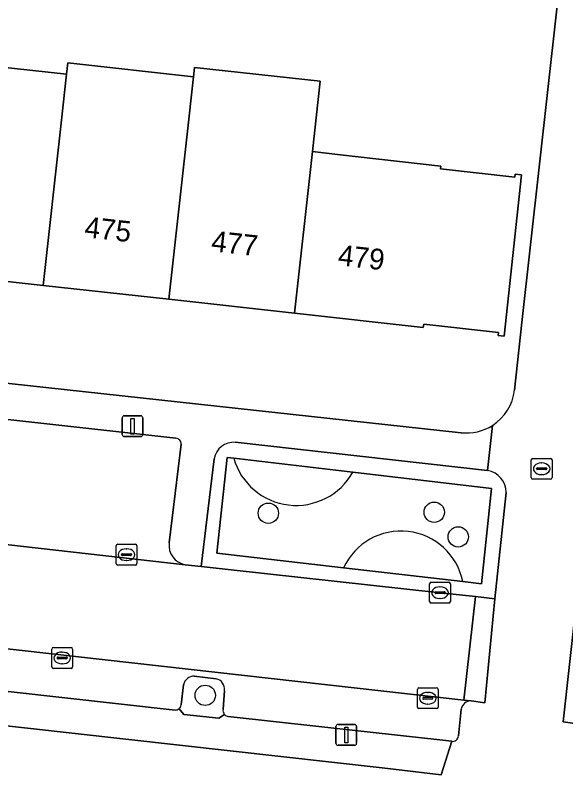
# Model space of a CAD drawing. Extents: x 161928 to 163071, y 386474 to 387428.
# Drawn here: x 162072.46 to 162098.94, y 387040.09 to 387076.6 of the extents above; entities that cross this region are included whole.
import ezdxf

# ---------------------------------------------------------------- set-up
doc = ezdxf.new("R2010")
doc.units = 0
for name, color, linetype in [('IMGEO_Boom', 7, 'Continuous'), ('IMGEO_Brandkraan', 7, 'Continuous'), ('IMGEO_Erf', 7, 'Continuous'), ('IMGEO_Groenvoorziening', 7, 'Continuous'), ('IMGEO_Kolk', 7, 'Continuous'), ('IMGEO_Lichtmast', 7, 'Continuous'), ('IMGEO_Pand', 7, 'Continuous'), ('IMGEO_Pand_nummerreeks', 7, 'Continuous'), ('IMGEO_Parkeervlak_open', 7, 'Continuous'), ('IMGEO_Rijbaan_lokaal_open', 7, 'Continuous'), ('IMGEO_Voetpad_open', 7, 'Continuous')]:
    doc.layers.add(name, color=color, linetype=linetype)

msp = doc.modelspace()

# ---------------------------------------------------------------- linework, layer by layer
at = {"layer": 'IMGEO_Boom'}
for centre in [(162084.633, 387052.664), (162092.612, 387052.707), (162093.767, 387051.525), (162081.599, 387043.908)]:
    msp.add_circle(centre, 0.489, dxfattribs=at)
at = {"layer": 'IMGEO_Brandkraan'}
for p, q in [((162097.352, 387055.299), (162098.204, 387055.299)), ((162097.277, 387054.373), (162097.277, 387055.225)), ((162097.765, 387055.079), (162097.79, 387055.079)), ((162098.278, 387055.225), (162098.278, 387054.373)), ((162097.536, 387054.793), (162097.536, 387054.805)), ((162097.974, 387054.756), (162097.576, 387054.756)), ((162097.579, 387054.842), (162097.977, 387054.842)), ((162097.788, 387054.519), (162097.763, 387054.519)), ((162098.02, 387054.805), (162098.02, 387054.793)), ((162098.204, 387054.299), (162097.352, 387054.299))]:
    msp.add_line(p, q, dxfattribs=at)
for points in [[(162097.352, 387055.299), (162098.204, 387055.299)], [(162097.277, 387054.373), (162097.277, 387055.225)], [(162098.278, 387055.225), (162098.278, 387054.373)], [(162098.204, 387054.299), (162097.352, 387054.299)]]:
    msp.add_lwpolyline(points, dxfattribs=at)
for centre, radius, start, end in [((162097.354, 387055.223), 0.0765, 91.552, 178.448), ((162097.354, 387055.223), 0.0765, 91.552, 178.448), ((162098.202, 387055.223), 0.0765, 1.552, 88.448), ((162098.202, 387055.223), 0.0765, 1.552, 88.448), ((162097.576, 387054.802), 0.0403, 85.8775, 175.7526), ((162097.573, 387054.792), 0.0366, 178.938, 274.7102), ((162097.977, 387054.799), 0.043, 264.8664, 352.4533), ((162097.981, 387054.804), 0.0386, 1.7309, 96.639), ((162097.354, 387054.375), 0.0765, 181.552, 268.448), ((162097.354, 387054.375), 0.0765, 181.552, 268.448), ((162098.202, 387054.375), 0.0765, 271.552, 358.448), ((162098.202, 387054.375), 0.0765, 271.552, 358.448)]:
    msp.add_arc(centre, radius, start, end, dxfattribs=at)
for centre, major_axis, ratio, start_param, end_param in [((162097.764, 387054.799), (-0.387, 0.002), 0.722429, 4.712389, 7.853982), ((162097.789, 387054.799), (-0.39, 0.002), 0.717154, 1.570796, 4.712389)]:
    msp.add_ellipse(centre, major_axis=major_axis, ratio=ratio, start_param=start_param, end_param=end_param, dxfattribs=at)
at = {"layer": 'IMGEO_Erf'}
for points in [[(162096.466, 387058.574), (162096.828, 387061.825), (162098.906, 387080.512)], [(162068.886, 387074.43), (162074.93, 387073.76), (162074.99, 387074.308), (162081.034, 387073.639), (162081.084, 387074.093), (162087.129, 387073.423), (162086.755, 387070.048), (162087.961, 387069.911), (162092.929, 387069.349), (162092.914, 387069.214), (162096.491, 387068.817), (162096.507, 387068.965), (162096.805, 387068.934), (162095.977, 387061.165), (162095.679, 387061.197), (162095.695, 387061.347), (162092.103, 387061.743), (162092.086, 387061.59), (162085.894, 387062.276), (162079.85, 387062.945), (162073.806, 387063.615), (162067.762, 387064.284)], [(162054.959, 387060.765), (162093.91, 387056.533)], [(162092.941, 387040.089), (162090.107, 387040.42), (162053.258, 387044.538), (162053.273, 387044.667), (162053.232, 387044.673), (162052.938, 387041.772), (162059.112, 387041.065), (162065.136, 387040.375), (162071.16, 387039.686), (162077.183, 387038.996), (162083.207, 387038.307), (162089.378, 387037.6), (162089.04, 387034.471), (162092.569, 387034.041), (162091.726, 387026.452), (162088.106, 387026.85), (162088.494, 387030.02)]]:
    msp.add_lwpolyline(points, dxfattribs=at)
for centre, radius, start, end in [((162094.168, 387058.829), 2.312, 302.701, 353.6728), ((162094.172, 387058.826), 2.307, 263.4876, 302.6627)]:
    msp.add_arc(centre, radius, start, end, dxfattribs=at)
at = {"layer": 'IMGEO_Groenvoorziening'}
for points in [[(162095.178, 387054.709), (162083.034, 387056.07)], [(162082.033, 387055.276), (162081.394, 387050.101), (162082.851, 387049.942), (162092.891, 387048.842), (162094.599, 387048.655), (162095.518, 387048.554), (162096.065, 387053.656)], [(162082.966, 387055.308), (162082.647, 387055.346), (162082.154, 387050.736), (162088.254, 387050.035)], [(162088.696, 387054.635), (162082.966, 387055.308)], [(162093.984, 387049.377), (162094.888, 387049.273), (162095.365, 387053.851), (162088.696, 387054.635)], [(162088.254, 387050.035), (162093.984, 387049.377)], [(162082.123, 387044.704), (162081.073, 387044.832)], [(162080.556, 387044.415), (162080.434, 387043.446)], [(162082.454, 387043.229), (162082.525, 387044.14)], [(162080.337, 387043.267), (162080.564, 387042.994), (162082.252, 387042.814), (162082.524, 387042.994)]]:
    msp.add_lwpolyline(points, dxfattribs=at)
msp.add_lwpolyline([(162093.984, 387049.377), (162088.254, 387050.035), (162082.154, 387050.736), (162082.647, 387055.346), (162082.966, 387055.308), (162088.696, 387054.635), (162095.365, 387053.851), (162094.888, 387049.273)], close=True, dxfattribs=at)
for centre, radius, start, end in [((162082.962, 387055.133), 0.94, 85.5971, 171.2463), ((162085.971, 387056.162), 3.124, 195.8703, 330.732), ((162085.971, 387056.162), 3.124, 195.8703, 330.732), ((162095.025, 387053.68), 1.04, 358.6594, 81.5592), ((162091.012, 387048.774), 3.032, 11.4606, 155.4377), ((162091.012, 387048.774), 3.032, 11.4606, 155.4377), ((162081.071, 387044.306), 0.526, 89.7371, 168.0405), ((162082.019, 387044.205), 0.51, 352.7293, 78.2306), ((162080.147, 387043.486), 0.29, 310.984, 352.1095), ((162082.752, 387043.19), 0.301, 172.5508, 220.6239)]:
    msp.add_arc(centre, radius, start, end, dxfattribs=at)
at = {"layer": 'IMGEO_Kolk'}
for p, q in [((162077.312, 387050.244), (162077.312, 387051.096)), ((162077.387, 387051.17), (162078.239, 387051.17)), ((162077.8, 387050.95), (162077.825, 387050.95)), ((162078.313, 387051.096), (162078.313, 387050.244)), ((162077.571, 387050.664), (162077.571, 387050.676)), ((162078.009, 387050.627), (162077.611, 387050.627)), ((162077.614, 387050.713), (162078.012, 387050.713)), ((162078.055, 387050.676), (162078.055, 387050.664)), ((162078.239, 387050.17), (162077.387, 387050.17)), ((162077.823, 387050.39), (162077.798, 387050.39)), ((162092.39, 387048.416), (162092.39, 387049.268)), ((162092.465, 387049.342), (162093.317, 387049.342)), ((162092.878, 387049.122), (162092.903, 387049.122)), ((162093.391, 387049.268), (162093.391, 387048.416)), ((162092.649, 387048.836), (162092.649, 387048.848)), ((162093.087, 387048.799), (162092.689, 387048.799)), ((162092.692, 387048.885), (162093.09, 387048.885)), ((162093.133, 387048.848), (162093.133, 387048.836)), ((162093.317, 387048.342), (162092.465, 387048.342)), ((162092.901, 387048.562), (162092.876, 387048.562)), ((162074.22, 387045.28), (162074.22, 387046.132)), ((162074.295, 387046.206), (162075.147, 387046.206)), ((162075.221, 387046.132), (162075.221, 387045.28)), ((162074.522, 387045.749), (162074.92, 387045.749)), ((162074.708, 387045.986), (162074.733, 387045.986)), ((162074.479, 387045.7), (162074.479, 387045.712)), ((162074.917, 387045.663), (162074.519, 387045.663)), ((162074.731, 387045.426), (162074.706, 387045.426)), ((162074.963, 387045.712), (162074.963, 387045.7)), ((162075.147, 387045.206), (162074.295, 387045.206)), ((162091.799, 387043.345), (162091.799, 387044.197)), ((162091.874, 387044.271), (162092.726, 387044.271)), ((162092.287, 387044.051), (162092.312, 387044.051)), ((162092.8, 387044.197), (162092.8, 387043.345)), ((162092.058, 387043.765), (162092.058, 387043.777)), ((162092.496, 387043.728), (162092.098, 387043.728)), ((162092.101, 387043.814), (162092.499, 387043.814)), ((162092.542, 387043.777), (162092.542, 387043.765)), ((162092.726, 387043.271), (162091.874, 387043.271)), ((162092.31, 387043.491), (162092.285, 387043.491))]:
    msp.add_line(p, q, dxfattribs=at)
for points in [[(162077.312, 387050.244), (162077.312, 387051.096)], [(162077.387, 387051.17), (162078.239, 387051.17)], [(162078.313, 387051.096), (162078.313, 387050.244)], [(162078.239, 387050.17), (162077.387, 387050.17)], [(162092.39, 387048.416), (162092.39, 387049.268)], [(162092.465, 387049.342), (162093.317, 387049.342)], [(162093.391, 387049.268), (162093.391, 387048.416)], [(162093.317, 387048.342), (162092.465, 387048.342)], [(162074.22, 387045.28), (162074.22, 387046.132)], [(162074.295, 387046.206), (162075.147, 387046.206)], [(162075.221, 387046.132), (162075.221, 387045.28)], [(162075.147, 387045.206), (162074.295, 387045.206)], [(162091.799, 387043.345), (162091.799, 387044.197)], [(162091.874, 387044.271), (162092.726, 387044.271)], [(162092.8, 387044.197), (162092.8, 387043.345)], [(162092.726, 387043.271), (162091.874, 387043.271)]]:
    msp.add_lwpolyline(points, dxfattribs=at)
for centre, radius, start, end in [((162077.389, 387051.094), 0.0765, 91.552, 178.448), ((162077.389, 387051.094), 0.0765, 91.552, 178.448), ((162078.237, 387051.094), 0.0765, 1.552, 88.448), ((162078.237, 387051.094), 0.0765, 1.552, 88.448), ((162077.611, 387050.673), 0.0403, 85.8775, 175.7526), ((162077.608, 387050.663), 0.0366, 178.938, 274.7102), ((162078.012, 387050.67), 0.043, 264.8664, 352.4533), ((162078.016, 387050.675), 0.0386, 1.7309, 96.639), ((162077.389, 387050.246), 0.0765, 181.552, 268.448), ((162077.389, 387050.246), 0.0765, 181.552, 268.448), ((162078.237, 387050.246), 0.0765, 271.552, 358.448), ((162078.237, 387050.246), 0.0765, 271.552, 358.448), ((162092.467, 387049.266), 0.0765, 91.552, 178.448), ((162092.467, 387049.266), 0.0765, 91.552, 178.448), ((162093.315, 387049.266), 0.0765, 1.552, 88.448), ((162093.315, 387049.266), 0.0765, 1.552, 88.448), ((162092.689, 387048.845), 0.0403, 85.8775, 175.7526), ((162092.686, 387048.835), 0.0366, 178.938, 274.7102), ((162093.09, 387048.842), 0.043, 264.8664, 352.4533), ((162093.094, 387048.847), 0.0386, 1.7309, 96.639), ((162092.467, 387048.418), 0.0765, 181.552, 268.448), ((162092.467, 387048.418), 0.0765, 181.552, 268.448), ((162093.315, 387048.418), 0.0765, 271.552, 358.448), ((162093.315, 387048.418), 0.0765, 271.552, 358.448), ((162074.297, 387046.13), 0.0765, 91.552, 178.448), ((162074.297, 387046.13), 0.0765, 91.552, 178.448), ((162075.145, 387046.13), 0.0765, 1.552, 88.448), ((162075.145, 387046.13), 0.0765, 1.552, 88.448), ((162074.519, 387045.709), 0.0403, 85.8775, 175.7526), ((162074.924, 387045.711), 0.0386, 1.7309, 96.639), ((162074.516, 387045.699), 0.0366, 178.938, 274.7102), ((162074.92, 387045.706), 0.043, 264.8664, 352.4533), ((162074.297, 387045.282), 0.0765, 181.552, 268.448), ((162074.297, 387045.282), 0.0765, 181.552, 268.448), ((162075.145, 387045.282), 0.0765, 271.552, 358.448), ((162075.145, 387045.282), 0.0765, 271.552, 358.448), ((162091.876, 387044.195), 0.0765, 91.552, 178.448), ((162091.876, 387044.195), 0.0765, 91.552, 178.448), ((162092.724, 387044.195), 0.0765, 1.552, 88.448), ((162092.724, 387044.195), 0.0765, 1.552, 88.448), ((162092.098, 387043.774), 0.0403, 85.8775, 175.7526), ((162092.095, 387043.764), 0.0366, 178.938, 274.7102), ((162092.499, 387043.771), 0.043, 264.8664, 352.4533), ((162092.503, 387043.776), 0.0386, 1.7309, 96.639), ((162091.876, 387043.347), 0.0765, 181.552, 268.448), ((162091.876, 387043.347), 0.0765, 181.552, 268.448), ((162092.724, 387043.347), 0.0765, 271.552, 358.448), ((162092.724, 387043.347), 0.0765, 271.552, 358.448)]:
    msp.add_arc(centre, radius, start, end, dxfattribs=at)
for centre, major_axis, ratio, start_param, end_param in [((162077.799, 387050.67), (-0.387, 0.002), 0.722429, 4.712389, 7.853982), ((162077.824, 387050.67), (-0.39, 0.002), 0.717154, 1.570796, 4.712389), ((162092.877, 387048.842), (-0.387, 0.002), 0.722429, 4.712389, 7.853982), ((162092.902, 387048.842), (-0.39, 0.002), 0.717154, 1.570796, 4.712389), ((162074.707, 387045.706), (-0.387, 0.002), 0.722429, 4.712389, 7.853982), ((162074.732, 387045.706), (-0.39, 0.002), 0.717154, 1.570796, 4.712389), ((162092.286, 387043.771), (-0.387, 0.002), 0.722429, 4.712389, 7.853982), ((162092.311, 387043.771), (-0.39, 0.002), 0.717154, 1.570796, 4.712389)]:
    msp.add_ellipse(centre, major_axis=major_axis, ratio=ratio, start_param=start_param, end_param=end_param, dxfattribs=at)
at = {"layer": 'IMGEO_Lichtmast'}
for p, q in [((162077.603, 387056.445), (162077.603, 387057.245)), ((162077.603, 387057.245), (162077.603, 387056.445)), ((162077.703, 387057.345), (162078.493, 387057.345)), ((162078.493, 387057.345), (162077.703, 387057.345)), ((162078.593, 387057.245), (162078.593, 387056.445)), ((162078.593, 387056.445), (162078.593, 387057.245)), ((162078.493, 387056.345), (162077.703, 387056.345)), ((162077.703, 387056.345), (162078.493, 387056.345)), ((162087.985, 387042.508), (162088.775, 387042.508)), ((162088.775, 387042.508), (162087.985, 387042.508)), ((162087.885, 387041.608), (162087.885, 387042.408)), ((162087.885, 387042.408), (162087.885, 387041.608)), ((162088.875, 387042.408), (162088.875, 387041.608)), ((162088.875, 387041.608), (162088.875, 387042.408)), ((162088.775, 387041.508), (162087.985, 387041.508)), ((162087.985, 387041.508), (162088.775, 387041.508))]:
    msp.add_line(p, q, dxfattribs=at)
for points in [[(162078.023, 387057.22), (162078.173, 387057.22), (162078.173, 387056.47), (162078.023, 387056.47), (162078.023, 387057.22)], [(162088.305, 387042.383), (162088.455, 387042.383), (162088.455, 387041.633), (162088.305, 387041.633), (162088.305, 387042.383)]]:
    msp.add_lwpolyline(points, dxfattribs=at)
for centre, start, end in [((162077.703, 387057.245), 90, 180), ((162077.703, 387057.245), 90, 180), ((162078.493, 387057.245), 0, 90), ((162078.493, 387057.245), 360, 90), ((162077.703, 387056.445), 180, 270), ((162077.703, 387056.445), 180, 270), ((162078.493, 387056.445), 270, 0), ((162078.493, 387056.445), 270, 0), ((162087.985, 387042.408), 90, 180), ((162087.985, 387042.408), 90, 180), ((162088.775, 387042.408), 0, 90), ((162088.775, 387042.408), 360, 90), ((162087.985, 387041.608), 180, 270), ((162087.985, 387041.608), 180, 270), ((162088.775, 387041.608), 270, 0), ((162088.775, 387041.608), 270, 0)]:
    msp.add_arc(centre, 0.1, start, end, dxfattribs=at)
at = {"layer": 'IMGEO_Pand'}
for points in [[(162074.67, 387071.416), (162074.93, 387073.76), (162068.886, 387074.43), (162068.857, 387074.171), (162067.762, 387064.284), (162073.806, 387063.615)], [(162080.712, 387070.732), (162081.034, 387073.639), (162074.99, 387074.308), (162074.93, 387073.76), (162074.67, 387071.416), (162073.806, 387063.615), (162079.85, 387062.945)], [(162086.755, 387070.048), (162087.129, 387073.423), (162081.084, 387074.093), (162081.034, 387073.639), (162080.712, 387070.732), (162079.85, 387062.945), (162085.894, 387062.276)], [(162092.929, 387069.349), (162087.961, 387069.911), (162086.755, 387070.048), (162085.894, 387062.276), (162092.086, 387061.59), (162092.103, 387061.743), (162095.695, 387061.347), (162095.679, 387061.197), (162095.977, 387061.165), (162096.805, 387068.934), (162096.507, 387068.965), (162096.491, 387068.817), (162092.914, 387069.214)]]:
    msp.add_lwpolyline(points, close=True, dxfattribs=at)
at = {"layer": 'IMGEO_Parkeervlak_open'}
for points in [[(162080.189, 387056.264), (162058.518, 387058.674)], [(162079.86, 387051.239), (162080.436, 387055.983)], [(162056.591, 387052.9), (162080.632, 387050.187)], [(162094.381, 387043.64), (162094.028, 387043.682), (162055.527, 387047.995)], [(162081.073, 387044.832), (162082.123, 387044.704)], [(162069.371, 387044.404), (162080.154, 387043.201)], [(162080.434, 387043.446), (162080.556, 387044.415)], [(162082.525, 387044.14), (162082.454, 387043.229)], [(162093.775, 387041.96), (162093.906, 387043.242)], [(162082.699, 387042.892), (162093.455, 387041.698)]]:
    msp.add_lwpolyline(points, dxfattribs=at)
for centre, radius, start, end in [((162080.176, 387056.003), 0.261, 355.5732, 87.058), ((162080.807, 387051.124), 0.953, 173.0923, 259.4532), ((162081.071, 387044.306), 0.526, 89.7371, 168.0405), ((162082.019, 387044.205), 0.51, 352.7293, 78.2306), ((162094.383, 387043.156), 0.484, 90.1936, 169.7254), ((162080.153, 387043.489), 0.288, 270.0996, 309.5646), ((162080.147, 387043.486), 0.29, 310.984, 352.1095), ((162082.752, 387043.19), 0.301, 172.5508, 220.6239), ((162082.757, 387043.193), 0.306, 220.4431, 259.0847), ((162093.492, 387041.979), 0.283, 262.426, 356.1918)]:
    msp.add_arc(centre, radius, start, end, dxfattribs=at)
at = {"layer": 'IMGEO_Rijbaan_lokaal_open'}
for points in [[(162094.599, 387048.655), (162092.891, 387048.842), (162082.851, 387049.942), (162081.394, 387050.101), (162080.632, 387050.187), (162056.591, 387052.9), (162056.026, 387052.968)], [(162055.527, 387047.995), (162094.028, 387043.682), (162094.599, 387048.655)]]:
    msp.add_lwpolyline(points, dxfattribs=at)
at = {"layer": 'IMGEO_Voetpad_open'}
for points in [[(162106.703, 387146.717), (162104.183, 387124.301), (162101.9, 387124.604), (162101.718, 387123.058), (162097.649, 387086.723), (162097.645, 387085.295), (162097.329, 387082.251), (162097.16, 387080.725), (162098.906, 387080.512), (162096.828, 387061.825), (162096.466, 387058.574)], [(162093.91, 387056.533), (162054.959, 387060.765), (162054.883, 387060.773), (162053.084, 387060.96), (162052.968, 387059.431), (162054.986, 387059.213), (162053.523, 387046.789), (162053.273, 387044.667), (162053.258, 387044.538), (162090.107, 387040.42), (162092.941, 387040.089), (162093.455, 387041.698), (162082.699, 387042.892)], [(162058.518, 387058.674), (162080.189, 387056.264)], [(162083.034, 387056.07), (162095.178, 387054.709), (162095.417, 387056.883)], [(162095.417, 387056.883), (162095.178, 387054.709)], [(162080.436, 387055.983), (162079.86, 387051.239)], [(162080.632, 387050.187), (162081.394, 387050.101), (162082.033, 387055.276)], [(162096.065, 387053.656), (162095.518, 387048.554), (162095.044, 387043.55), (162094.381, 387043.64)], [(162099.532, 387039.652), (162099.825, 387042.491), (162098.809, 387042.63), (162099.476, 387048.578), (162100.525, 387048.493), (162100.852, 387052.069)], [(162080.154, 387043.201), (162069.371, 387044.404)], [(162082.524, 387042.994), (162082.252, 387042.814), (162080.564, 387042.994), (162080.337, 387043.267)], [(162093.906, 387043.242), (162093.775, 387041.96)], [(162093.455, 387041.698), (162092.941, 387040.089)]]:
    msp.add_lwpolyline(points, dxfattribs=at)
for points in [[(162095.518, 387048.554), (162094.599, 387048.655), (162094.028, 387043.682), (162094.381, 387043.64), (162095.044, 387043.55)], [(162100.525, 387048.493), (162099.476, 387048.578), (162098.809, 387042.63), (162099.825, 387042.491)]]:
    msp.add_lwpolyline(points, close=True, dxfattribs=at)
for centre, radius, start, end in [((162094.168, 387058.829), 2.312, 302.701, 353.6728), ((162094.172, 387058.826), 2.307, 263.4876, 302.6627), ((162080.176, 387056.003), 0.261, 355.5732, 87.058), ((162082.962, 387055.133), 0.94, 85.5971, 171.2463), ((162095.025, 387053.68), 1.04, 358.6594, 81.5592), ((162080.807, 387051.124), 0.953, 173.0923, 259.4532), ((162094.383, 387043.156), 0.484, 90.1936, 169.7254), ((162080.153, 387043.489), 0.288, 270.0996, 309.5646), ((162082.757, 387043.193), 0.306, 220.4431, 259.0847), ((162093.492, 387041.979), 0.283, 262.426, 356.1918)]:
    msp.add_arc(centre, radius, start, end, dxfattribs=at)

# ---------------------------------------------------------------- texts
at = {"layer": 'IMGEO_Pand_nummerreeks'}
for s, rotation, p in [('475', 353.6803, (162075.761, 387065.934)), ('477', 353.6803, (162081.854, 387065.259)), ('479', 353.6789, (162087.947, 387064.584))]:
    msp.add_text(s, height=1, rotation=rotation, dxfattribs=at).set_placement(p)

doc.saveas('drawing.dxf')
